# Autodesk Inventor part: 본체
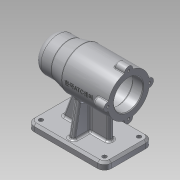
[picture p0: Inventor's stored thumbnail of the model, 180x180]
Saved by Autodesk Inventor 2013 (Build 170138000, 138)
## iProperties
Created: 2019-07
Part Number: 본체
Material: 알루미늄 6061
Document SubType Name: Modeling
Designer: Administrator
Density: 2.71 g/cm^3
Mass: 646.956 g
Surface Area: 654.842 cm^2
Volume: 238.729 cm^3
Author: Administrator
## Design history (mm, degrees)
sketch "스케치1"
  geometry: L1 (-45, 0)-(67, 0); L2 (-45, 0)-(-45, 25); L3 (-45, 25)-(-20, 25); L4 (-20, 25)-(0, 30); L5 (0, 30)-(67, 30); L6 (67, 30)-(67, 21); L7 (67, 21)-(52, 21); L8 (52, 21)-(52, 24); L9 (52, 24)-(-2, 24); L10 (-2, 24)-(-2, 21); L11 (-2, 21)-(-14, 21); L12 (-14, 21)-(-14, 17.5); L13 (-14, 17.5)-(-32, 17.5); L14 (-32, 17.5)-(-32, 16); L15 (-32, 16)-(-36, 16); L16 (-36, 16)-(-36, 10.5); L17 (-36, 10.5)-(-39, 10.5); L18 (-39, 10.5)-(-39, 0); 2 further points
  constraints: 36 end point, 8 horizontal, 8 vertical, 2 point on line, 1 collinear, 1 midpoint, 1 vertical alignment
  dimensions: "d0" = 112 distance of L1.start L1.end; "d2" = 45 distance of L1.start point (0, 0); "d3" = 48 diameter of L9 L1; "d4" = 42 diameter of L7 L1; "d5" = 60 diameter of L5 L1; "d6" = 25 distance of L2.end L3.end; "d7" = 45 distance from line of L4.end L2; "d8" = 50 diameter of L3 L1; "d10" = 42 diameter of L11 L1; "d11" = 35 diameter of L13 L1; "d12" = 32 diameter of L15 L1; "d13" = 21 diameter of L17 L1; "d14" = 54 distance between parallel lines of L10 L8; "d15" = 15 distance of L6.end L7.end; "d16" = 12 distance of L10.end L11.end; "d17" = 18 distance of L12.end L13.end; "d18" = 4 distance of L14.end L15.end; "d19" = 3 distance of L16.end L17.end
revolve "회전1" sketch "스케치1" stored, may be unused: angle "d20" = 90 deg
sketch "스케치2"
  geometry: C1 r 21 at (0, 0) reference; C2 r 6 at (0, 30); 1 further point
  constraints: 2 vertical alignment, 1 centre point, 1 other
  dimensions: "d21" = 12 diameter of C2
extrude "돌출1" join sketch "스케치2" distance "d23" = 16; taper "d24" = 0 deg
sketch "스케치3"
  geometry: A1 r 6 centre (0, 0) between (5.97, -0.6) and (-5.97, -0.6) reference; 1 further point
  constraints: 1 coincident
hole "구멍1" sketch "스케치3" at (0, 0) diameter "d25" = 3.242; stored, may be unused: countersink angle "d29" = 90 deg, drill point angle "d31" = 118 deg; dims "d26" = 8, "d27" = 4, "d28" = 2, "d30" = 11
node "작업 평면1"
sketch "스케치4"
  geometry: L1 (-67, -5.97)-(-67, -29.4) reference; L2 (-67, -35)-(45, -35); L3 (45, -35)-(45, 35); L4 (45, 35)-(-67, 35); L5 (-67, 35)-(-67, -35); 2 further points
  constraints: 8 end point, 2 parallel, 1 collinear, 1 horizontal, 1 horizontal alignment, 1 midpoint, 1 perpendicular
  dimensions: "d36" = 112 distance of L2.start L2.end; "d38" = 70 distance of L4.end L2.start
extrude "돌출2" join sketch "스케치4" distance "d39" = 10; taper "d40" = 0 deg
sketch "스케치5"
  geometry: L1 (67, 35)-(11, 35); L2 (11, 35)-(11, 0); L3 (7, -4)-(15, -4); L4 (15, -4)-(15, 4); L5 (15, 4)-(7, 4); L6 (7, 4)-(7, -4); L7 (7, -4)-(15, 4); L8 (15, -4)-(7, 4); 2 further points
  constraints: 16 end point, 3 midpoint, 2 horizontal, 2 parallel, 1 horizontal alignment, 1 perpendicular, 1 vertical
  dimensions: "d41" = 56 distance of L1.start L1.end; "d42" = 8 distance of L3.end L4.end; "d43" = 8 distance of L3.start L3.end
extrude "돌출3" join sketch "스케치5" stored distance "d44" = 10; taper "d45" = 0 deg
node "작업 평면2"
sketch "스케치6"
  geometry: L1 (39, 0)-(-31, 0) reference; L2 (39, -10)-(39, 0) reference; L3 (-31, -10)-(-31, 0) reference; L4 (32, 0)-(27.265, 26.851); L5 (-24, 0)-(-19.735, 24.186); 1 further point
  constraints: 4 end point, 2 point on line
  dimensions: "d46" = 7 distance from line of L2 L4.start; "d47" = 7 distance of L1.end L5.start; "d48" = 100 deg angle of L1 L5; "d49" = 100 deg angle of L1 L4
feature "리브1" dims "d50" = 1, "d51" = 8, "d52" = 0, "d53" = 0, "d54" = 1, "d55" = 1
feature "리브2" dims "d56" = 1, "d57" = 8, "d58" = 0, "d59" = 0, "d60" = 1, "d61" = 1
sketch "스케치7"
  geometry: L1 (67, -70)-(-45, -70) reference; L2 (-45, -80)-(-45, -70) reference; L3 (-25, -70)-(-13.875, -39.433); L4 (42, -70)-(42, -33.942); L5 (67, -80)-(67, -70) reference; 1 further point
  constraints: 4 end point, 2 point on line, 1 vertical
  dimensions: "d62" = 110 deg angle of L1 L3; "d63" = 20 distance from line of L2 L3.start; "d64" = 25 distance from line of L5 L4.start
feature "리브3" dims "d65" = 1, "d66" = 8, "d67" = 0, "d68" = 0, "d69" = 1, "d70" = 1
feature "리브4" dims "d71" = 1, "d72" = 8, "d73" = 0, "d74" = 0, "d75" = 1, "d76" = 1
fillet "모깎기1" dims "d77" = 10
chamfer "모따기1" distance "d78" = 3; stored, may be unused: second distance "d79" = 2, angle "d80" = 45 deg
sketch "스케치8"
  geometry: A1 r 7 centre (57, 25) between (64, 25) and (57, 32) reference; A2 r 7 centre (-35, 25) between (-35, 32) and (-42, 25) reference; A3 r 7 centre (-35, -25) between (-42, -25) and (-35, -32) reference; A4 r 7 centre (57, -25) between (57, -32) and (64, -25) reference; 5 further points
  constraints: 4 coincident
hole "구멍2" sketch "스케치8" at (-35, 25), (57, 25), (57, -25), (-35, -25) diameter "d81" = 6; stored, may be unused: countersink angle "d85" = 90 deg, drill point angle "d87" = 118 deg; dims "d82" = 8, "d83" = 4, "d84" = 2, "d86" = 11
fillet "모깎기2" dims "d88" = 3
fillet "모깎기3" dims "d98" = 1
fillet "모깎기4" dims "d90" = 3
fillet "모깎기5" dims "d91" = 3
fillet "모깎기6" dims "d92" = 3, "d93" = 0.3
node "작업 평면3"
sketch "스케치9"
  geometry: L1 (67, 6.771)-(67, 29.226) reference; 2 further points
  constraints: 1 horizontal alignment, 1 other
  dimensions: "d95" = 42 distance from line of L1 point (25, 0)
feature "엠보싱1" sketch "스케치9" dims "d96" = 0.5, "d97" = 0
chamfer "모따기2" distance "d99" = 1; stored, may be unused: second distance "d100" = 2, angle "d101" = 45 deg
node "솔리드1"
pattern_circular "원형 패턴1" dims angle "d33" = 360 deg
other parameters: "d94" = 31
